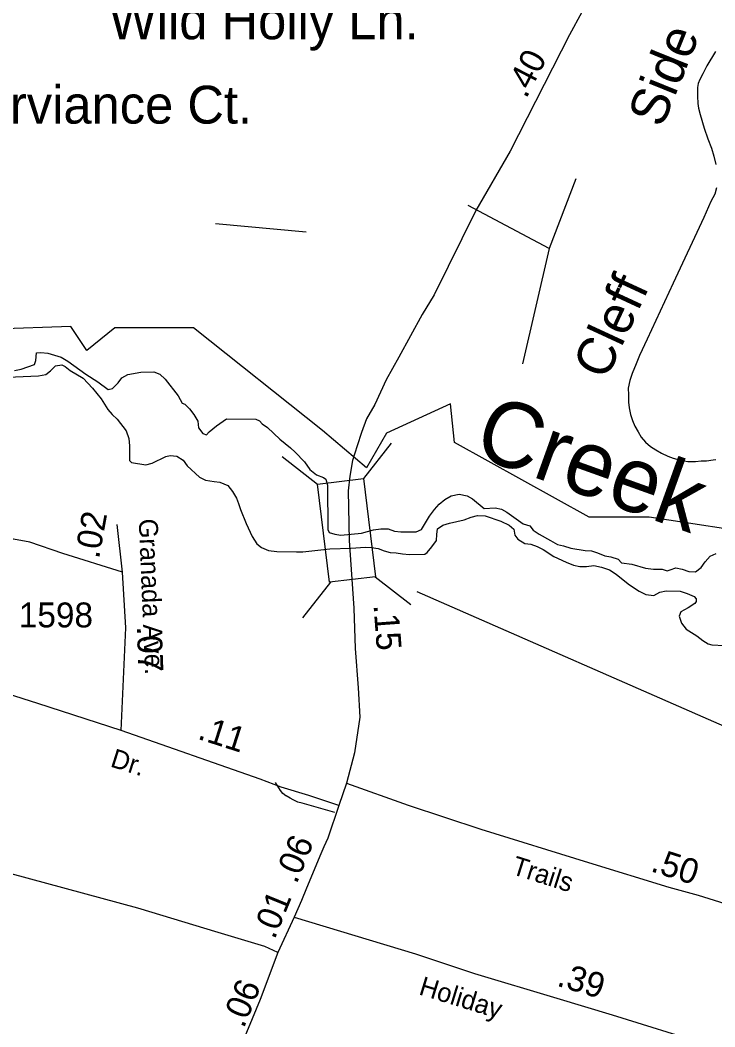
# Model space of a CAD drawing. Extents: x 2290055 to 2389491, y 66597 to 237875.
# Drawn here: x 2342158 to 2343900, y 150018 to 152543 of the extents above; entities that cross this region are included whole.
import ezdxf

# ---------------------------------------------------------------- set-up
doc = ezdxf.new("R2010")
doc.units = 0
for name, color, linetype in [('Exist Boundary Political City Limit New', 7, 'Continuous'), ('Exist Hydrographic River Shore', 7, 'Continuous'), ('Exist Hydrographic River Shore Label', 7, 'Continuous'), ('Exist Road Non-System Type 51', 7, 'Continuous'), ('Exist Road Non-System Type 51 Label', 7, 'Continuous'), ('Exist Road Primary US Structure Standard Bridge CELL', 7, 'Continuous'), ('Exist Road Secondary Mileage Hundredths English Label', 7, 'Continuous'), ('Exist Road Secondary Structure Standard Bridge CELL', 7, 'Continuous'), ('Exist Road Secondary Type 51 Attributed', 7, 'Continuous'), ('Exist Road Secondary Type 51 Label', 7, 'Continuous'), ('Exist Road Secondary Type 51 Number Label', 7, 'Continuous'), ('Map Preparation Boundary City Limit Buffer Line', 7, 'Continuous')]:
    doc.layers.add(name, color=color, linetype=linetype)

msp = doc.modelspace()

# ---------------------------------------------------------------- linework, layer by layer
at = {"layer": 'Exist Boundary Political City Limit New'}
msp.add_lwpolyline([(2344042, 151249.2), (2343734.8, 151296), (2343584.5, 151296), (2343247, 151483.2), (2343237, 151580.1), (2343076.5, 151506.6), (2343026.5, 151419.7), (2342916.2, 151513.2), (2342592.2, 151770.6), (2342395, 151770.6), (2342325, 151713.8), (2342284.8, 151774), (2342094.2, 151767.3), (2342010.8, 151837.5), (2341884, 151927.7), (2341703.5, 152074.8), (2341369.5, 152231.9), (2341139, 152409), (2341045.2, 152379), (2340898.2, 152469.2), (2340721.2, 152693.2)], dxfattribs=at)
at = {"layer": 'Exist Hydrographic River Shore'}
for points in [[(2342143.5, 151663.6), (2342160.5, 151666.8), (2342194, 151678.9), (2342197.5, 151688.9), (2342198.7, 151708.1), (2342210.2, 151709.1), (2342227.2, 151707), (2342261, 151697.3), (2342277.2, 151687.6), (2342323, 151655), (2342353, 151635.8), (2342379, 151616.1), (2342389.2, 151618.8), (2342403.5, 151632.7), (2342413.2, 151645.7), (2342428, 151653.7), (2342460.7, 151659.3), (2342493.2, 151660.6), (2342508.5, 151654.3), (2342521.5, 151641.9)], [(2342116.6, 151647.7), (2342127, 151647.5), (2342203.7, 151650.2), (2342222.7, 151653.7), (2342234.5, 151663.3)], [(2342234.5, 151663.3), (2342247, 151675.5), (2342262.5, 151678.2), (2342271, 151674), (2342283, 151663.7), (2342316, 151644.5), (2342339, 151619.6), (2342361, 151592.5), (2342378.2, 151565.8), (2342388.7, 151553.9), (2342401.5, 151542), (2342424, 151512.9), (2342430.7, 151493.4), (2342432.5, 151475.3), (2342432.5, 151438.1), (2342437.2, 151433.2), (2342472.7, 151427.4), (2342489, 151431.5), (2342523, 151448.4), (2342533.7, 151450.7), (2342551.2, 151449.1), (2342566.7, 151439.3), (2342576.5, 151424.8), (2342608, 151396.3), (2342623, 151388.4), (2342644, 151385.1), (2342659, 151384.1), (2342679, 151375.5), (2342690.2, 151360), (2342700, 151344), (2342705.7, 151330), (2342710.5, 151315.5), (2342724.7, 151280.3), (2342739.5, 151247.2), (2342751.5, 151229.3), (2342763.5, 151219.5), (2342780.7, 151212.1), (2342801.5, 151209.7), (2342850.5, 151209), (2342866.7, 151209.3), (2342934.7, 151216.4), (2342987, 151218.5), (2343023.5, 151220.5), (2343038.5, 151219.6), (2343055.5, 151217.3), (2343071, 151211.6), (2343085.5, 151207.4), (2343100.7, 151206.5), (2343116.5, 151204.1), (2343134, 151202.6), (2343172.5, 151203), (2343178, 151207), (2343190.5, 151221.2), (2343202, 151237.8), (2343202.5, 151252.7), (2343204, 151267), (2343217.7, 151275.9), (2343234.7, 151280.8), (2343271.5, 151289.6), (2343288.5, 151295.6), (2343305, 151300.3), (2343323.5, 151299.4), (2343363, 151286.2), (2343384.2, 151276.3), (2343395.5, 151265.8), (2343398, 151251.1), (2343406, 151240.9), (2343423, 151230.1), (2343438.5, 151228.4), (2343454, 151222.2), (2343469.5, 151214.5), (2343495.7, 151197.7), (2343526.7, 151183), (2343545.2, 151175.3), (2343561.5, 151172.1), (2343577.7, 151172.4), (2343596, 151174.6), (2343615.5, 151170.7), (2343635.7, 151164.1), (2343652.5, 151153.2), (2343682.5, 151128.7), (2343695.7, 151119.2), (2343710.2, 151110.5), (2343727, 151102.4), (2343746.5, 151099.9), (2343762, 151107.8), (2343778, 151110.9), (2343812.7, 151110.3), (2343830.5, 151104.9), (2343848, 151096.7), (2343852.7, 151090.8), (2343853.2, 151084.8), (2343849.2, 151079.7), (2343832.5, 151068.6), (2343814, 151058.9), (2343810.5, 151047.3), (2343815.7, 151030.3), (2343828, 151015.2), (2343854.2, 150998.2), (2343869.2, 150986.9)], [(2342521.5, 151641.9), (2342554, 151600.7), (2342564, 151581.9), (2342570.7, 151579.1), (2342582.2, 151567.6), (2342593.2, 151553.7), (2342603.5, 151537), (2342605.5, 151520.4), (2342616.2, 151505.9), (2342625, 151502.3), (2342631.7, 151509.7), (2342650.5, 151525), (2342675.2, 151542.5), (2342748.5, 151541.7), (2342758, 151538), (2342765, 151530.3), (2342778.2, 151521), (2342809.2, 151491.3), (2342835.7, 151469.7), (2342847.2, 151459.3), (2342870.5, 151434.4), (2342884, 151415.8), (2342901, 151402.3), (2342918.5, 151395.7), (2342924.2, 151391), (2342928.2, 151376), (2342929.5, 151265), (2342932.7, 151257.9), (2342947, 151253.2), (2342962, 151250.5), (2343013.5, 151256.2), (2343043.7, 151264.6), (2343062, 151266.8), (2343081, 151267), (2343096.5, 151261.1), (2343112, 151259.2), (2343151, 151259.4), (2343164, 151265.1), (2343174.5, 151281.5), (2343184, 151298.2), (2343197, 151315.4), (2343208.5, 151328.2), (2343222.7, 151340.3), (2343238.5, 151349.8), (2343259, 151353.4), (2343279, 151349.8), (2343292.2, 151341.6), (2343321, 151317.8), (2343348.5, 151319.4), (2343365, 151316), (2343378.2, 151308.7), (2343418.7, 151279.4), (2343435.7, 151274.5), (2343444.2, 151263.7), (2343459, 151253.4), (2343488, 151237.6), (2343505.2, 151227.2), (2343520.2, 151224.2), (2343539, 151218.3), (2343574.7, 151212.3), (2343590, 151211.7), (2343605.5, 151206.9), (2343624, 151198.6), (2343639, 151196.3), (2343657.2, 151190.4), (2343666, 151181.6), (2343691.7, 151178), (2343725.7, 151168.3), (2343746, 151165.7), (2343767.5, 151165.6), (2343780, 151161.5), (2343787.7, 151163.5), (2343802, 151169.2), (2343818, 151165.6), (2343834.2, 151159.5), (2343851, 151158.5), (2343865.5, 151169.9), (2343875, 151184.2), (2343887.5, 151198.3), (2343903.2, 151205.2)], [(2343869.2, 150986.9), (2343883, 150978.2), (2343892.2, 150975.4), (2343922.7, 150973.7)]]:
    msp.add_lwpolyline(points, dxfattribs=at)
at = {"layer": 'Exist Road Non-System Type 51'}
msp.add_line((2342647.5, 152032.2), (2342874.7, 152011.3), dxfattribs=at)
for points in [[(2343901.5, 152463.8), (2343879.7, 152427.9), (2343869.3, 152407.8), (2343862, 152393.7), (2343858.1, 152383.7), (2343855.9, 152373.8), (2343856, 152361.6), (2343856.1, 152351.8), (2343856.8, 152333.4), (2343858.3, 152321.7), (2343862.5, 152305.7), (2343872.7, 152271.7), (2343882, 152244.8), (2343891.1, 152221.9), (2343897.1, 152201.8), (2343901.9, 152180.6)], [(2343551.4, 152144.6), (2343484.3, 151970.2), (2343417.2, 151680.3)], [(2343903.6, 152121.9), (2343899.3, 152106.3), (2343889.8, 152087.9), (2343872.1, 152047.5), (2343794.9, 151883), (2343729.9, 151742.5), (2343711.1, 151701.8), (2343702.1, 151681), (2343692.6, 151656.4), (2343686.7, 151638.4), (2343682.6, 151619.6), (2343682.9, 151602.5), (2343683.3, 151584.1), (2343684.8, 151570.1), (2343688.1, 151553.5), (2343693, 151538.2), (2343699.4, 151524.4), (2343707.2, 151510.3), (2343715.3, 151496.5), (2343726, 151483.8), (2343738.6, 151473.1), (2343751.7, 151464.7), (2343765.5, 151456.8), (2343781.9, 151448.9), (2343795.2, 151444.2), (2343813.8, 151439), (2343832.3, 151435.8), (2343851.3, 151435.9), (2343865.7, 151437.4), (2343878.8, 151437.6), (2343895.4, 151440.2), (2343902, 151440.8)], [(2343484.3, 151970.2), (2343281.6, 152077.5)], [(2342824.2, 150597.1), (2342816.6, 150602.6), (2342810.4, 150610.6), (2342798.4, 150630.5)], [(2342946.8, 150555.6), (2342864.8, 150579), (2342854.2, 150581.5), (2342842.5, 150586.6), (2342834.8, 150590.9), (2342824.7, 150596.7), (2342824.2, 150597.1)]]:
    msp.add_lwpolyline(points, dxfattribs=at)
at = {"layer": 'Exist Road Primary US Structure Standard Bridge CELL'}
msp.add_line((2343152.7, 151109.8), (2344249.2, 150628.4), dxfattribs=at)
at = {"layer": 'Exist Road Secondary Structure Standard Bridge CELL'}
for p, q in [((2343088.3, 151481.9), (2343018.6, 151392.7)), ((2342814.5, 151448.4), (2342903.7, 151378.7)), ((2342935.9, 151132.9), (2342866.2, 151043.7)), ((2343048.2, 151146.6), (2343137.4, 151076.9))]:
    msp.add_line(p, q, dxfattribs=at)
msp.add_lwpolyline([(2343018.6, 151392.7), (2343048.8, 151146.7), (2342933.8, 151132.6), (2342903.7, 151378.7)], close=True, dxfattribs=at)
at = {"layer": 'Exist Road Secondary Type 51 Attributed'}
for p, q in [((2342414.8, 151158.4), (2342401.5, 151277.2)), ((2342975.9, 150628.9), (2342957.1, 150572.4))]:
    msp.add_line(p, q, dxfattribs=at)
for points in [[(2343889.6, 153308.6), (2343857.9, 153165.8), (2343816.2, 153047.1), (2343752.1, 152904.3), (2343535, 152505.6), (2343386.2, 152213.6), (2343300.4, 152065.3), (2343196.1, 151853.5), (2343166, 151804.5), (2343107.6, 151697.1), (2343075.6, 151640.6), (2343047, 151578.3), (2343026.1, 151542.4), (2343013.5, 151508.7), (2343003.1, 151475.1), (2342991.4, 151438.3), (2342984.7, 151399), (2342980.5, 151362.3), (2342983, 151237.7)], [(2342414.8, 151158.4), (2342265.4, 151204.7), (2342182.5, 151233), (2342141.1, 151240.5), (2342084.6, 151263.1), (2342058.3, 151276.3), (2342043.2, 151287.6), (2341964.1, 151330.9), (2341896.4, 151387.4), (2341834.2, 151434.5), (2341743.3, 151499.7)], [(2342983, 151237.7), (2342994.7, 151068.1), (2342998.1, 150966.9), (2343005.2, 150867.9), (2343009.4, 150794.3), (2342996, 150704.9), (2342975.9, 150628.9)], [(2342410.9, 150760.9), (2342423.3, 151018.2), (2342414.8, 151158.4)], [(2342410.9, 150760.9), (2342202.4, 150829), (2341895.2, 150926.4), (2341794.1, 150956.5), (2341586.4, 151021.3)], [(2342957.1, 150572.4), (2342881.9, 150597.5), (2342812.5, 150618.4), (2342759.9, 150638.5), (2342410.9, 150760.9)], [(2342804.2, 150203.9), (2342771.6, 150218.9), (2342654.1, 150254.4), (2342453.1, 150315), (2342135.5, 150401.1), (2341917, 150460.9), (2341752.7, 150513.1), (2341561.8, 150569.5), (2341302.7, 150638.9)], [(2342975.9, 150628.9), (2343130.5, 150573.7), (2343313.2, 150513.1), (2343582.7, 150429.9), (2343784.5, 150367.7), (2343858.1, 150347.6), (2344034.4, 150292.4), (2344337.4, 150194.2), (2344534.7, 150134.1), (2344694.3, 150078.9), (2344973.5, 149994.5), (2345201.2, 149923), (2345375.9, 149867.9)], [(2342957.1, 150572.4), (2342929.3, 150491.2), (2342919.7, 150469.5), (2342911.5, 150451.2), (2342875.9, 150365.1), (2342863.3, 150334.5), (2342844.6, 150292.6)], [(2342844.6, 150292.6), (2342804.2, 150203.9)], [(2342844.6, 150292.6), (2343149.3, 150200.5), (2343297.3, 150151.2), (2343503.7, 150089.3), (2343642.5, 150047.6), (2343879, 149974), (2344434.8, 149804.3), (2344698.5, 149724.5)], [(2342804.2, 150203.9), (2342759.9, 150086.1), (2342705.3, 149954.9), (2342683.1, 149899.7)]]:
    msp.add_lwpolyline(points, dxfattribs=at)
at = {"layer": 'Map Preparation Boundary City Limit Buffer Line'}
msp.add_lwpolyline([(2344042, 151249.2), (2343734.8, 151296), (2343584.5, 151296), (2343247, 151483.2), (2343237, 151580.1), (2343076.5, 151506.6), (2343026.5, 151419.7), (2342916.2, 151513.2), (2342592.2, 151770.6), (2342395, 151770.6), (2342325, 151713.8), (2342284.8, 151774), (2342094.2, 151767.3), (2342010.8, 151837.5), (2341884, 151927.7), (2341703.5, 152074.8), (2341369.5, 152231.9), (2341139, 152409), (2341045.2, 152379), (2340898.2, 152469.2), (2340721.2, 152693.2)], dxfattribs=at)

# ---------------------------------------------------------------- texts
at = {"layer": 'Exist Hydrographic River Shore Label'}
msp.add_text('Creek', height=164.04, rotation=340.2723, dxfattribs=at).set_placement((2343288.5, 151452.6))
at = {"layer": 'Exist Road Non-System Type 51 Label'}
for s, p in [('Wild Holly Ln.', (2342380.6, 152494.7)), ('Purviance Ct.', (2341977, 152283.1))]:
    msp.add_text(s, height=95, dxfattribs=at).set_placement(p)
for s, rotation, p in [('Side', 68.0288, (2343767.2, 152269.8)), ('Cleff', 65.1574, (2343626.7, 151636.9))]:
    msp.add_text(s, height=95, rotation=rotation, dxfattribs=at).set_placement(p)
at = {"layer": 'Exist Road Secondary Mileage Hundredths English Label'}
for s, rotation, p in [('.40', 62.732, (2343426.7, 152344.1)), ('.02', 79.6904, (2342355.6, 151189.8)), ('.15', 274.2032, (2343043.9, 151075.5)), ('.07', 272.1654, (2342450.4, 151021.9)), ('.11', 342.2697, (2342600.5, 150740.4)), ('.06', 67.5037, (2342850.9, 150374)), ('.50', 342.1717, (2343736.3, 150408.5)), ('.01', 67.8012, (2342795.7, 150234.8)), ('.39', 343.1113, (2343501.1, 150121.3)), ('.06', 67.8012, (2342718.6, 150012.1))]:
    msp.add_text(s, height=62.5, rotation=rotation, dxfattribs=at).set_placement(p)
at = {"layer": 'Exist Road Secondary Type 51 Label'}
for s, rotation, p in [('Granada Ave.', 272.3855, (2342455.2, 151291.3)), ('Dr.', 342.4967, (2342381.8, 150671.1)), ('Trails', 342.4481, (2343387.5, 150401.6)), ('Holiday', 342.933, (2343155.2, 150099.5))]:
    msp.add_text(s, height=47.5, rotation=rotation, dxfattribs=at).set_placement(p)
at = {"layer": 'Exist Road Secondary Type 51 Number Label'}
msp.add_text('1598', height=62.5, dxfattribs=at).set_placement((2342154.7, 151019.5))

doc.saveas('drawing.dxf')
